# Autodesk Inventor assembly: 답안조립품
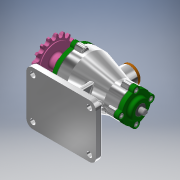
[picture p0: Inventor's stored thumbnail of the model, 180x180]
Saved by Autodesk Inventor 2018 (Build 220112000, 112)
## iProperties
Created: 2020-12
Part Number: 답안조립품
Material: 일반
Document SubType Name: Assembly
Designer: home
Author: home
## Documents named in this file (15)
- C:\Users\home\Desktop\701206V1032\답안조립품.iam
- C:\Users\home\Desktop\701206V1032\본체.ipt
- C:\Users\home\Desktop\701206V1032\개스킷 A.ipt
- C:\Users\home\Desktop\701206V1032\개스킷 B.ipt
- C:\Users\home\Desktop\701206V1032\축.ipt
- C:\Users\home\Desktop\701206V1032\베어링 6200.ipt
- C:\Users\home\Desktop\701206V1032\앞커버.ipt
- C:\Users\home\Desktop\701206V1032\뒤커버.ipt
- C:\Users\home\Desktop\701206V1032\오일 실 17 30 8.ipt
- C:\Users\home\Desktop\701206V1032\오일 실 10 20 7.ipt
- C:\Users\home\Desktop\701206V1032\키 4x4x14.ipt
- C:\Users\home\Desktop\701206V1032\스프로킷.ipt
- C:\Users\home\Desktop\701206V1032\마개.ipt
- C:\Users\home\Desktop\701206V1032\볼트 M5.ipt
- C:\Users\home\Desktop\701206V1032\베어링 6203.ipt
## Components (2 placed, 2 different names)
1. 개스킷 A:1
2. 개스킷 B:1
